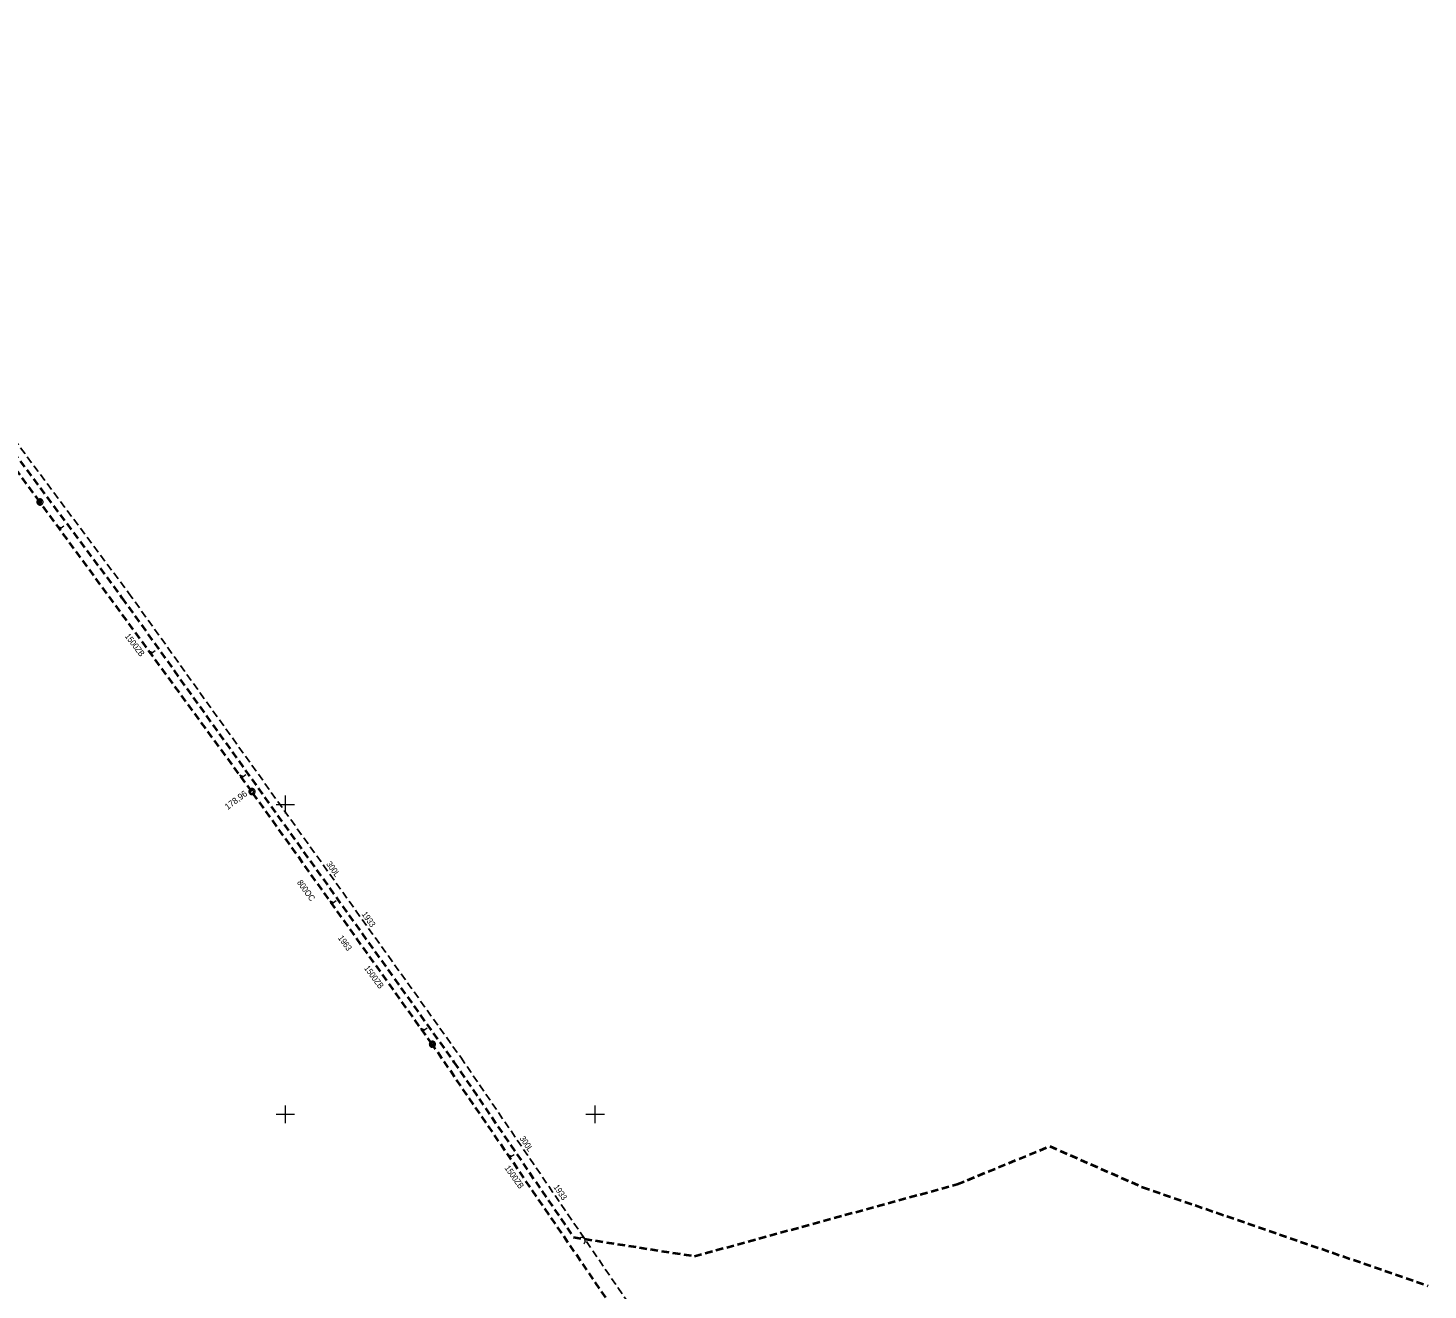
# Model space of a CAD drawing. Extents: x -740851 to -738888, y -1041382 to -1040235.
# Drawn here: x -739641.5 to -739415.5, y -1040778.4 to -1040574.7 of the extents above; entities that cross this region are included whole.
import ezdxf

# ---------------------------------------------------------------- set-up
doc = ezdxf.new("R2010")
doc.units = 0
doc.header["$LTSCALE"] = 0.4
doc.linetypes.add('MEDIUM_DASHED', pattern=[4.5, 3, -1.5])
for name, color, linetype, lineweight in [('1', 7, 'Continuous', 13), ('18', 7, 'Continuous', 13), ('8', 7, 'Continuous', 13)]:
    doc.layers.add(name, color=color, linetype=linetype, lineweight=lineweight)

msp = doc.modelspace()

# ---------------------------------------------------------------- linework, layer by layer
at = {"layer": '1'}
for p, q in [((-739600, -1040698.571), (-739600, -1040701.429)), ((-739600, -1040698.571), (-739600, -1040701.429)), ((-739601.48, -1040700), (-739598.48, -1040700)), ((-739601.48, -1040700), (-739598.48, -1040700)), ((-739601.48, -1040750), (-739598.48, -1040750)), ((-739600, -1040748.571), (-739600, -1040751.429)), ((-739551.48, -1040750), (-739548.48, -1040750)), ((-739550, -1040748.571), (-739550, -1040751.429))]:
    msp.add_line(p, q, dxfattribs=at)
at = {"layer": '18', "linetype": 'MEDIUM_DASHED', "lineweight": 40}
for p, q in [((-739639.62, -1040651.16), (-739669.06, -1040610.98)), ((-739547.23, -1040781.07), (-739576.27, -1040738.69))]:
    msp.add_line(p, q, dxfattribs=at)
at = {"layer": '18'}
for points in [[(-739639.09, -1040651.17), (-739639.1, -1040651.12), (-739639.1, -1040651.07), (-739639.12, -1040651.02), (-739639.14, -1040650.97), (-739639.16, -1040650.92), (-739639.19, -1040650.88), (-739639.22, -1040650.84), (-739639.26, -1040650.8), (-739639.3, -1040650.77), (-739639.34, -1040650.74), (-739639.39, -1040650.72), (-739639.44, -1040650.7), (-739639.49, -1040650.68), (-739639.54, -1040650.68), (-739639.59, -1040650.67), (-739639.64, -1040650.68), (-739639.69, -1040650.68), (-739639.74, -1040650.7), (-739639.79, -1040650.72), (-739639.84, -1040650.74), (-739639.88, -1040650.77), (-739639.92, -1040650.8), (-739639.96, -1040650.84), (-739639.99, -1040650.88), (-739640.02, -1040650.92), (-739640.04, -1040650.97), (-739640.06, -1040651.02), (-739640.08, -1040651.07), (-739640.08, -1040651.12), (-739640.09, -1040651.17), (-739640.08, -1040651.22), (-739640.08, -1040651.27), (-739640.06, -1040651.32), (-739640.04, -1040651.37), (-739640.02, -1040651.42), (-739639.99, -1040651.46), (-739639.96, -1040651.5), (-739639.92, -1040651.54), (-739639.88, -1040651.57), (-739639.84, -1040651.6), (-739639.79, -1040651.62), (-739639.74, -1040651.64), (-739639.69, -1040651.66), (-739639.64, -1040651.66), (-739639.59, -1040651.67), (-739639.54, -1040651.66), (-739639.49, -1040651.66), (-739639.44, -1040651.64), (-739639.39, -1040651.62), (-739639.34, -1040651.6), (-739639.3, -1040651.57), (-739639.26, -1040651.54), (-739639.22, -1040651.5), (-739639.19, -1040651.46), (-739639.16, -1040651.42), (-739639.14, -1040651.37), (-739639.12, -1040651.32), (-739639.1, -1040651.27), (-739639.1, -1040651.22)], [(-739639.32, -1040651.16), (-739639.32, -1040651.13), (-739639.326, -1040651.1), (-739639.332, -1040651.07), (-739639.344, -1040651.04), (-739639.362, -1040651.01), (-739639.38, -1040650.986), (-739639.398, -1040650.962), (-739639.422, -1040650.938), (-739639.446, -1040650.92), (-739639.47, -1040650.902), (-739639.5, -1040650.884), (-739639.53, -1040650.872), (-739639.56, -1040650.866), (-739639.59, -1040650.86), (-739639.62, -1040650.86), (-739639.65, -1040650.86), (-739639.68, -1040650.866), (-739639.71, -1040650.872), (-739639.74, -1040650.884), (-739639.77, -1040650.902), (-739639.794, -1040650.92), (-739639.818, -1040650.938), (-739639.842, -1040650.962), (-739639.86, -1040650.986), (-739639.878, -1040651.01), (-739639.896, -1040651.04), (-739639.908, -1040651.07), (-739639.914, -1040651.1), (-739639.92, -1040651.13), (-739639.92, -1040651.16), (-739639.92, -1040651.19), (-739639.914, -1040651.22), (-739639.908, -1040651.25), (-739639.896, -1040651.28), (-739639.878, -1040651.31), (-739639.86, -1040651.334), (-739639.842, -1040651.358), (-739639.818, -1040651.382), (-739639.794, -1040651.4), (-739639.77, -1040651.418), (-739639.74, -1040651.436), (-739639.71, -1040651.448), (-739639.68, -1040651.454), (-739639.65, -1040651.46), (-739639.62, -1040651.46), (-739639.59, -1040651.46), (-739639.56, -1040651.454), (-739639.53, -1040651.448), (-739639.5, -1040651.436), (-739639.47, -1040651.418), (-739639.446, -1040651.4), (-739639.422, -1040651.382), (-739639.398, -1040651.358), (-739639.38, -1040651.334), (-739639.362, -1040651.31), (-739639.344, -1040651.28), (-739639.332, -1040651.25), (-739639.326, -1040651.22), (-739639.32, -1040651.19)], [(-739604.86, -1040697.91), (-739604.87, -1040697.86), (-739604.87, -1040697.81), (-739604.89, -1040697.76), (-739604.91, -1040697.71), (-739604.93, -1040697.66), (-739604.96, -1040697.62), (-739604.99, -1040697.58), (-739605.03, -1040697.54), (-739605.07, -1040697.51), (-739605.11, -1040697.48), (-739605.16, -1040697.46), (-739605.21, -1040697.44), (-739605.26, -1040697.42), (-739605.31, -1040697.42), (-739605.36, -1040697.41), (-739605.41, -1040697.42), (-739605.46, -1040697.42), (-739605.51, -1040697.44), (-739605.56, -1040697.46), (-739605.61, -1040697.48), (-739605.65, -1040697.51), (-739605.69, -1040697.54), (-739605.73, -1040697.58), (-739605.76, -1040697.62), (-739605.79, -1040697.66), (-739605.81, -1040697.71), (-739605.83, -1040697.76), (-739605.85, -1040697.81), (-739605.85, -1040697.86), (-739605.86, -1040697.91), (-739605.85, -1040697.96), (-739605.85, -1040698.01), (-739605.83, -1040698.06), (-739605.81, -1040698.11), (-739605.79, -1040698.16), (-739605.76, -1040698.2), (-739605.73, -1040698.24), (-739605.69, -1040698.28), (-739605.65, -1040698.31), (-739605.61, -1040698.34), (-739605.56, -1040698.36), (-739605.51, -1040698.38), (-739605.46, -1040698.4), (-739605.41, -1040698.4), (-739605.36, -1040698.41), (-739605.31, -1040698.4), (-739605.26, -1040698.4), (-739605.21, -1040698.38), (-739605.16, -1040698.36), (-739605.11, -1040698.34), (-739605.07, -1040698.31), (-739605.03, -1040698.28), (-739604.99, -1040698.24), (-739604.96, -1040698.2), (-739604.93, -1040698.16), (-739604.91, -1040698.11), (-739604.89, -1040698.06), (-739604.87, -1040698.01), (-739604.87, -1040697.96)], [(-739605.09, -1040697.9), (-739605.09, -1040697.87), (-739605.096, -1040697.84), (-739605.102, -1040697.81), (-739605.114, -1040697.78), (-739605.132, -1040697.75), (-739605.15, -1040697.726), (-739605.168, -1040697.702), (-739605.192, -1040697.678), (-739605.216, -1040697.66), (-739605.24, -1040697.642), (-739605.27, -1040697.624), (-739605.3, -1040697.612), (-739605.33, -1040697.606), (-739605.36, -1040697.6), (-739605.39, -1040697.6), (-739605.42, -1040697.6), (-739605.45, -1040697.606), (-739605.48, -1040697.612), (-739605.51, -1040697.624), (-739605.54, -1040697.642), (-739605.564, -1040697.66), (-739605.588, -1040697.678), (-739605.612, -1040697.702), (-739605.63, -1040697.726), (-739605.648, -1040697.75), (-739605.666, -1040697.78), (-739605.678, -1040697.81), (-739605.684, -1040697.84), (-739605.69, -1040697.87), (-739605.69, -1040697.9), (-739605.69, -1040697.93), (-739605.684, -1040697.96), (-739605.678, -1040697.99), (-739605.666, -1040698.02), (-739605.648, -1040698.05), (-739605.63, -1040698.074), (-739605.612, -1040698.098), (-739605.588, -1040698.122), (-739605.564, -1040698.14), (-739605.54, -1040698.158), (-739605.51, -1040698.176), (-739605.48, -1040698.188), (-739605.45, -1040698.194), (-739605.42, -1040698.2), (-739605.39, -1040698.2), (-739605.36, -1040698.2), (-739605.33, -1040698.194), (-739605.3, -1040698.188), (-739605.27, -1040698.176), (-739605.24, -1040698.158), (-739605.216, -1040698.14), (-739605.192, -1040698.122), (-739605.168, -1040698.098), (-739605.15, -1040698.074), (-739605.132, -1040698.05), (-739605.114, -1040698.02), (-739605.102, -1040697.99), (-739605.096, -1040697.96), (-739605.09, -1040697.93)], [(-739575.74, -1040738.7), (-739575.75, -1040738.65), (-739575.75, -1040738.6), (-739575.77, -1040738.55), (-739575.79, -1040738.5), (-739575.81, -1040738.45), (-739575.84, -1040738.41), (-739575.87, -1040738.37), (-739575.91, -1040738.33), (-739575.95, -1040738.3), (-739575.99, -1040738.27), (-739576.04, -1040738.25), (-739576.09, -1040738.23), (-739576.14, -1040738.21), (-739576.19, -1040738.21), (-739576.24, -1040738.2), (-739576.29, -1040738.21), (-739576.34, -1040738.21), (-739576.39, -1040738.23), (-739576.44, -1040738.25), (-739576.49, -1040738.27), (-739576.53, -1040738.3), (-739576.57, -1040738.33), (-739576.61, -1040738.37), (-739576.64, -1040738.41), (-739576.67, -1040738.45), (-739576.69, -1040738.5), (-739576.71, -1040738.55), (-739576.73, -1040738.6), (-739576.73, -1040738.65), (-739576.74, -1040738.7), (-739576.73, -1040738.75), (-739576.73, -1040738.8), (-739576.71, -1040738.85), (-739576.69, -1040738.9), (-739576.67, -1040738.95), (-739576.64, -1040738.99), (-739576.61, -1040739.03), (-739576.57, -1040739.07), (-739576.53, -1040739.1), (-739576.49, -1040739.13), (-739576.44, -1040739.15), (-739576.39, -1040739.17), (-739576.34, -1040739.19), (-739576.29, -1040739.19), (-739576.24, -1040739.2), (-739576.19, -1040739.19), (-739576.14, -1040739.19), (-739576.09, -1040739.17), (-739576.04, -1040739.15), (-739575.99, -1040739.13), (-739575.95, -1040739.1), (-739575.91, -1040739.07), (-739575.87, -1040739.03), (-739575.84, -1040738.99), (-739575.81, -1040738.95), (-739575.79, -1040738.9), (-739575.77, -1040738.85), (-739575.75, -1040738.8), (-739575.75, -1040738.75)], [(-739575.97, -1040738.69), (-739575.97, -1040738.66), (-739575.976, -1040738.63), (-739575.982, -1040738.6), (-739575.994, -1040738.57), (-739576.012, -1040738.54), (-739576.03, -1040738.516), (-739576.048, -1040738.492), (-739576.072, -1040738.468), (-739576.096, -1040738.45), (-739576.12, -1040738.432), (-739576.15, -1040738.414), (-739576.18, -1040738.402), (-739576.21, -1040738.396), (-739576.24, -1040738.39), (-739576.27, -1040738.39), (-739576.3, -1040738.39), (-739576.33, -1040738.396), (-739576.36, -1040738.402), (-739576.39, -1040738.414), (-739576.42, -1040738.432), (-739576.444, -1040738.45), (-739576.468, -1040738.468), (-739576.492, -1040738.492), (-739576.51, -1040738.516), (-739576.528, -1040738.54), (-739576.546, -1040738.57), (-739576.558, -1040738.6), (-739576.564, -1040738.63), (-739576.57, -1040738.66), (-739576.57, -1040738.69), (-739576.57, -1040738.72), (-739576.564, -1040738.75), (-739576.558, -1040738.78), (-739576.546, -1040738.81), (-739576.528, -1040738.84), (-739576.51, -1040738.864), (-739576.492, -1040738.888), (-739576.468, -1040738.912), (-739576.444, -1040738.93), (-739576.42, -1040738.948), (-739576.39, -1040738.966), (-739576.36, -1040738.978), (-739576.33, -1040738.984), (-739576.3, -1040738.99), (-739576.27, -1040738.99), (-739576.24, -1040738.99), (-739576.21, -1040738.984), (-739576.18, -1040738.978), (-739576.15, -1040738.966), (-739576.12, -1040738.948), (-739576.096, -1040738.93), (-739576.072, -1040738.912), (-739576.048, -1040738.888), (-739576.03, -1040738.864), (-739576.012, -1040738.84), (-739575.994, -1040738.81), (-739575.982, -1040738.78), (-739575.976, -1040738.75), (-739575.97, -1040738.72)]]:
    msp.add_lwpolyline(points, close=True, dxfattribs=at)
at = {"layer": '18', "linetype": 'MEDIUM_DASHED', "lineweight": 40}
msp.add_lwpolyline([(-739576.27, -1040738.69), (-739605.39, -1040697.9), (-739639.62, -1040651.16)], dxfattribs=at)
at = {"layer": '18'}
for points in [[(-739635.749, -1040655.065), (-739636.405, -1040655.546), (-739636.749, -1040655.078), (-739636.109, -1040655.329)], [(-739636.2, -1040655.343), (-739636.391, -1040655.483), (-739636.611, -1040655.184), (-739636.198, -1040655.346)], [(-739636.294, -1040655.359), (-739636.39, -1040655.429), (-739636.503, -1040655.275), (-739636.292, -1040655.362)], [(-739621.007, -1040675.194), (-739621.664, -1040675.675), (-739622.007, -1040675.207), (-739621.368, -1040675.458)], [(-739621.459, -1040675.472), (-739621.65, -1040675.612), (-739621.869, -1040675.313), (-739621.456, -1040675.475)], [(-739621.553, -1040675.488), (-739621.648, -1040675.558), (-739621.761, -1040675.405), (-739621.551, -1040675.491)], [(-739606.354, -1040695.203), (-739607.011, -1040695.684), (-739607.354, -1040695.215), (-739606.714, -1040695.467)], [(-739606.806, -1040695.48), (-739606.997, -1040695.621), (-739607.216, -1040695.321), (-739606.803, -1040695.484)], [(-739606.9, -1040695.496), (-739606.995, -1040695.567), (-739607.108, -1040695.413), (-739606.897, -1040695.5)], [(-739591.77, -1040715.574), (-739592.433, -1040716.047), (-739592.77, -1040715.574), (-739592.134, -1040715.834)], [(-739592.225, -1040715.846), (-739592.418, -1040715.984), (-739592.633, -1040715.682), (-739592.223, -1040715.849)], [(-739592.319, -1040715.861), (-739592.416, -1040715.93), (-739592.526, -1040715.775), (-739592.317, -1040715.864)], [(-739577.099, -1040736.124), (-739577.762, -1040736.597), (-739578.099, -1040736.125), (-739577.463, -1040736.384)], [(-739577.554, -1040736.397), (-739577.747, -1040736.534), (-739577.962, -1040736.232), (-739577.552, -1040736.4)], [(-739577.648, -1040736.412), (-739577.745, -1040736.48), (-739577.855, -1040736.325), (-739577.646, -1040736.415)], [(-739563.06, -1040756.524), (-739563.732, -1040756.984), (-739564.06, -1040756.505), (-739563.429, -1040756.776)], [(-739563.521, -1040756.787), (-739563.716, -1040756.921), (-739563.926, -1040756.615), (-739563.518, -1040756.79)], [(-739563.615, -1040756.8), (-739563.713, -1040756.867), (-739563.821, -1040756.71), (-739563.613, -1040756.803)]]:
    msp.add_lwpolyline(points, dxfattribs=at)
at = {"layer": '8', "linetype": 'MEDIUM_DASHED', "lineweight": 40}
msp.add_lwpolyline([(-739697.47, -1040574.66), (-739686.88, -1040585.368), (-739626.36, -1040666.625), (-739572.757, -1040741.567), (-739553.461, -1040769.846), (-739533.944, -1040772.907), (-739491.526, -1040761.298), (-739476.568, -1040755.167), (-739461.603, -1040761.762), (-739415.52, -1040777.67)], dxfattribs=at)
at = {"layer": '8', "linetype": 'MEDIUM_DASHED', "lineweight": 25}
msp.add_lwpolyline([(-739693.286, -1040576.71), (-739686.808, -1040583.233), (-739625.283, -1040665.839), (-739571.664, -1040740.804), (-739523.94, -1040810.745), (-739502.47, -1040846.1), (-739496.554, -1040855.122)], dxfattribs=at)
at = {"layer": '8'}
msp.add_lwpolyline([(-739551.799, -1040770.893), (-739551.759, -1040770.853), (-739551.714, -1040770.822), (-739551.681, -1040770.773), (-739551.648, -1040770.724), (-739551.615, -1040770.675), (-739551.597, -1040770.623), (-739551.579, -1040770.571), (-739551.568, -1040770.51), (-739551.565, -1040770.455), (-739551.563, -1040770.4), (-739551.576, -1040770.342), (-739551.588, -1040770.284), (-739551.601, -1040770.226), (-739551.632, -1040770.181), (-739551.654, -1040770.129), (-739551.694, -1040770.09), (-739551.725, -1040770.045), (-739551.774, -1040770.012), (-739551.824, -1040769.978), (-739551.873, -1040769.945), (-739551.925, -1040769.928), (-739551.977, -1040769.91), (-739552.038, -1040769.898), (-739552.093, -1040769.896), (-739552.148, -1040769.893), (-739552.206, -1040769.906), (-739552.264, -1040769.919), (-739552.321, -1040769.932), (-739552.367, -1040769.963), (-739552.418, -1040769.985)], dxfattribs=at)

# ---------------------------------------------------------------- texts
at = {"layer": '18', "width": 0.9}
for rotation, p in [(307.218, (-739625.945, -1040672.867)), (306.523, (-739587.309, -1040726.455)), (305.42, (-739564.633, -1040758.698))]:
    msp.add_text('1500ZB', height=1, rotation=rotation, dxfattribs=at).set_placement(p)
at = {"layer": '18'}
msp.add_text('178,96', height=1, rotation=37.26, dxfattribs=at).set_placement((-739609.287, -1040700.917))
at = {"layer": '8', "width": 0.75}
for s, rotation, p in [('300L', 305.574, (-739593.438, -1040709.617)), ('800OC', 306.153, (-739598.154, -1040712.624)), ('1933', 305.574, (-739587.71, -1040717.729)), ('1963', 306.153, (-739591.538, -1040721.571)), ('300L', 304.308, (-739562.214, -1040753.924)), ('1933', 304.308, (-739556.742, -1040761.771))]:
    msp.add_text(s, height=1, rotation=rotation, dxfattribs=at).set_placement(p)

doc.saveas('drawing.dxf')
